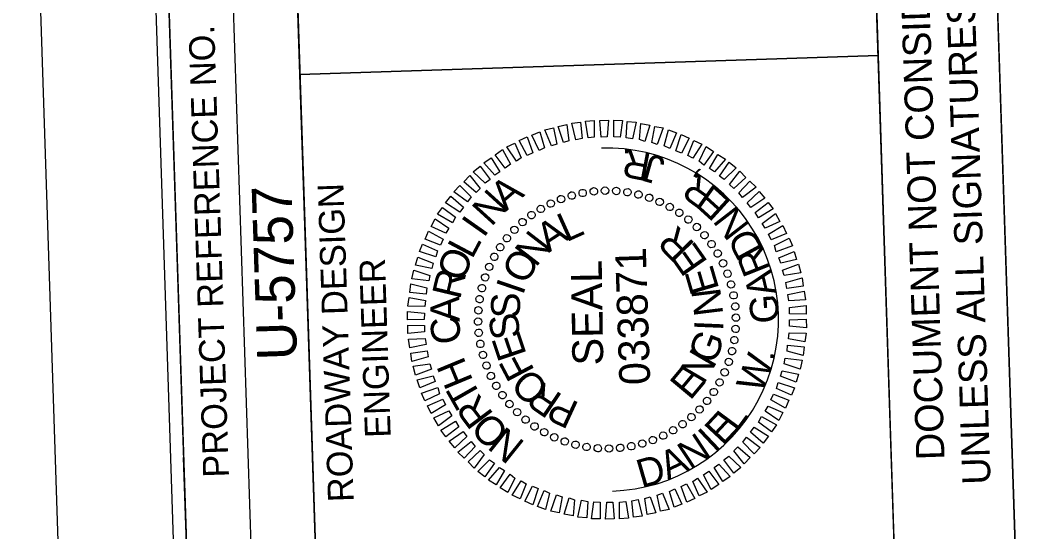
# Model space of a CAD drawing. Extents: x 1627314 to 1628469, y 762309 to 764253.
# Drawn here: x 1627314.2 to 1627512.6, y 763788.2 to 763887.6 of the extents above; entities that cross this region are included whole.
import ezdxf

# ---------------------------------------------------------------- set-up
doc = ezdxf.new("R2010")
doc.units = 0
for name, color, linetype in [('Old_Level_58', 7, 'Continuous'), ('Scratch_Level_0', 7, 'Continuous'), ('Sheet Data Field CELL', 7, 'Continuous'), ('Sheet Plot Border Inside CELL', 7, 'Continuous'), ('Sheet Plot Border Outside CELL', 7, 'Continuous'), ('Sheet Professional Seal CELL', 7, 'Continuous'), ('Sheet Profile CELL', 7, 'Continuous'), ('Sheet Profile Grid Major CELL', 7, 'Continuous'), ('Sheet Profile Grid Minor CELL', 7, 'Continuous'), ('Sheet Sticker Exception Certification CELL', 7, 'Continuous')]:
    doc.layers.add(name, color=color, linetype=linetype)

msp = doc.modelspace()

# ---------------------------------------------------------------- linework, layer by layer
at = {"layer": 'Old_Level_58'}
msp.add_lwpolyline([(1627507.79, 763781.61), (1627501.25, 763981.49), (1627565.16, 763983.58), (1627571.7, 763783.7)], close=True, dxfattribs=at)
at = {"layer": 'Scratch_Level_0'}
msp.add_arc((1627428.29, 763829.42), 33.36, 271.8735, 91.8735, dxfattribs=at)
at = {"layer": 'Sheet Plot Border Inside CELL'}
msp.add_lwpolyline([(1628446.34, 762357.53), (1628391.86, 764023.14), (1627337.33, 763988.65), (1627391.81, 762323.04)], close=True, dxfattribs=at)
at = {"layer": 'Sheet Plot Border Outside CELL'}
msp.add_lwpolyline([(1628469.21, 762345.27), (1628413.63, 764044.37), (1627314.22, 764008.4), (1627369.79, 762309.31)], close=True, dxfattribs=at)
at = {"layer": 'Sheet Professional Seal CELL'}
for p, q in [((1627425.73, 763854.4), (1627425.73, 763854.4)), ((1627427.92, 763854.52), (1627427.92, 763854.52)), ((1627430.13, 763854.45), (1627430.13, 763854.45)), ((1627419.32, 763852.89), (1627419.32, 763852.89)), ((1627421.4, 763853.56), (1627421.4, 763853.56)), ((1627423.59, 763854.03), (1627423.59, 763854.03)), ((1627432.29, 763854.17), (1627432.29, 763854.17)), ((1627434.4, 763853.79), (1627434.4, 763853.79)), ((1627436.52, 763853.16), (1627436.52, 763853.16)), ((1627438.55, 763852.32), (1627438.55, 763852.32)), ((1627415.43, 763850.96), (1627415.43, 763850.96)), ((1627417.35, 763852.03), (1627417.35, 763852.03)), ((1627440.53, 763851.39), (1627440.53, 763851.39)), ((1627411.86, 763848.45), (1627411.86, 763848.45)), ((1627413.57, 763849.75), (1627413.57, 763849.75)), ((1627442.37, 763850.19), (1627442.37, 763850.19)), ((1627444.16, 763848.9), (1627444.16, 763848.9)), ((1627410.26, 763846.89), (1627410.26, 763846.89)), ((1627445.76, 763847.45), (1627445.76, 763847.45)), ((1627408.81, 763845.3), (1627408.81, 763845.3)), ((1627447.32, 763845.85), (1627447.32, 763845.85)), ((1627407.52, 763843.5), (1627407.52, 763843.5)), ((1627448.62, 763844.15), (1627448.62, 763844.15)), ((1627406.33, 763841.66), (1627406.33, 763841.66)), ((1627449.83, 763842.28), (1627449.83, 763842.28)), ((1627450.9, 763840.37), (1627450.9, 763840.37)), ((1627405.4, 763839.68), (1627405.4, 763839.68)), ((1627451.76, 763838.4), (1627451.76, 763838.4)), ((1627404.56, 763837.65), (1627404.56, 763837.65)), ((1627403.93, 763835.53), (1627403.93, 763835.53)), ((1627452.43, 763836.32), (1627452.43, 763836.32)), ((1627403.55, 763833.42), (1627403.55, 763833.42)), ((1627452.9, 763834.13), (1627452.9, 763834.13)), ((1627403.27, 763831.26), (1627403.27, 763831.26)), ((1627453.27, 763831.99), (1627453.27, 763831.99)), ((1627403.19, 763829.05), (1627403.19, 763829.05)), ((1627428.29, 763829.42), (1627428.29, 763829.42)), ((1627453.39, 763829.79), (1627453.39, 763829.79)), ((1627403.31, 763826.86), (1627403.31, 763826.86)), ((1627453.32, 763827.59), (1627453.32, 763827.59)), ((1627403.68, 763824.72), (1627403.68, 763824.72)), ((1627453.04, 763825.43), (1627453.04, 763825.43)), ((1627404.16, 763822.53), (1627404.16, 763822.53)), ((1627452.66, 763823.32), (1627452.66, 763823.32)), ((1627452.02, 763821.2), (1627452.02, 763821.2)), ((1627404.82, 763820.45), (1627404.82, 763820.45)), ((1627451.19, 763819.17), (1627451.19, 763819.17)), ((1627405.69, 763818.48), (1627405.69, 763818.48)), ((1627406.75, 763816.56), (1627406.75, 763816.56)), ((1627450.26, 763817.19), (1627450.26, 763817.19)), ((1627407.96, 763814.7), (1627407.96, 763814.7)), ((1627449.06, 763815.35), (1627449.06, 763815.35)), ((1627409.27, 763812.99), (1627409.27, 763812.99)), ((1627447.77, 763813.55), (1627447.77, 763813.55)), ((1627410.82, 763811.39), (1627410.82, 763811.39)), ((1627446.32, 763811.95), (1627446.32, 763811.95)), ((1627412.42, 763809.94), (1627412.42, 763809.94)), ((1627414.21, 763808.65), (1627414.21, 763808.65)), ((1627443.02, 763809.09), (1627443.02, 763809.09)), ((1627444.72, 763810.4), (1627444.72, 763810.4)), ((1627416.05, 763807.46), (1627416.05, 763807.46)), ((1627439.24, 763806.82), (1627439.24, 763806.82)), ((1627441.15, 763807.88), (1627441.15, 763807.88)), ((1627418.04, 763806.53), (1627418.04, 763806.53)), ((1627420.06, 763805.69), (1627420.06, 763805.69)), ((1627422.19, 763805.06), (1627422.19, 763805.06)), ((1627424.3, 763804.68), (1627424.3, 763804.68)), ((1627433, 763804.81), (1627433, 763804.81)), ((1627435.19, 763805.29), (1627435.19, 763805.29)), ((1627437.27, 763805.95), (1627437.27, 763805.95)), ((1627426.46, 763804.4), (1627426.46, 763804.4)), ((1627428.66, 763804.32), (1627428.66, 763804.32)), ((1627430.86, 763804.44), (1627430.86, 763804.44))]:
    msp.add_line(p, q, dxfattribs=at)
for points in [[(1627424.64, 763864.77), (1627424.13, 763868.01), (1627425.83, 763868.16), (1627425.83, 763864.91)], [(1627427.13, 763864.9), (1627426.88, 763868.15), (1627428.58, 763868.2), (1627428.33, 763864.94)], [(1627429.63, 763864.94), (1627429.63, 763868.19), (1627431.28, 763868.14), (1627430.84, 763864.88)], [(1627417.48, 763863.19), (1627416.23, 763866.35), (1627417.87, 763866.7), (1627418.52, 763863.57)], [(1627419.86, 763863.87), (1627418.81, 763866.98), (1627420.5, 763867.34), (1627420.9, 763864.2)], [(1627422.25, 763864.39), (1627421.44, 763867.62), (1627423.14, 763867.83), (1627423.44, 763864.63)], [(1627432.04, 763864.76), (1627432.24, 763867.97), (1627433.94, 763867.83), (1627433.25, 763864.55)], [(1627434.6, 763864.45), (1627434.9, 763867.56), (1627436.61, 763867.27), (1627435.66, 763864.08)], [(1627437.02, 763863.88), (1627437.57, 763867), (1627439.23, 763866.7), (1627438.08, 763863.51)], [(1627439.44, 763863.21), (1627440.24, 763866.33), (1627441.81, 763865.74), (1627440.51, 763862.69)], [(1627412.79, 763861.33), (1627411.2, 763864.23), (1627412.77, 763864.94), (1627413.87, 763861.87)], [(1627415.11, 763862.31), (1627413.71, 763865.32), (1627415.24, 763865.92), (1627416.14, 763862.84)], [(1627441.68, 763862.28), (1627442.72, 763865.41), (1627444.3, 763864.72), (1627442.79, 763861.81)], [(1627444.01, 763861.35), (1627445.16, 763864.24), (1627446.74, 763863.54), (1627444.98, 763860.79)], [(1627408.52, 763858.89), (1627406.53, 763861.48), (1627408, 763862.48), (1627409.5, 763859.63)], [(1627410.68, 763860.26), (1627408.83, 763863.01), (1627410.36, 763863.71), (1627411.61, 763860.89)], [(1627446.2, 763860.23), (1627447.6, 763863.07), (1627449.04, 763862.12), (1627447.12, 763859.46)], [(1627406.51, 763857.53), (1627404.33, 763859.91), (1627405.75, 763860.9), (1627407.44, 763858.16)], [(1627448.24, 763858.79), (1627449.85, 763861.55), (1627451.33, 763860.64), (1627449.21, 763858.17)], [(1627404.61, 763855.96), (1627402.29, 763858.19), (1627403.6, 763859.28), (1627405.59, 763856.7)], [(1627450.19, 763857.35), (1627452.06, 763860.02), (1627453.39, 763858.96), (1627451.11, 763856.68)], [(1627452.15, 763855.67), (1627454.11, 763858.28), (1627455.3, 763857.07), (1627452.97, 763854.89)], [(1627402.87, 763854.16), (1627400.45, 763856.23), (1627401.61, 763857.47), (1627403.65, 763854.93)], [(1627453.95, 763854.08), (1627456.08, 763856.35), (1627457.32, 763855.19), (1627454.68, 763853.15)], [(1627401.18, 763852.3), (1627398.52, 763854.26), (1627399.68, 763855.5), (1627401.9, 763853.27)], [(1627455.57, 763852.13), (1627457.89, 763854.35), (1627458.99, 763853.04), (1627456.25, 763851.2)], [(1627399.69, 763850.35), (1627396.88, 763852.11), (1627397.94, 763853.44), (1627400.36, 763851.32)], [(1627398.26, 763848.25), (1627395.31, 763849.91), (1627396.31, 763851.24), (1627398.83, 763849.37)], [(1627457.13, 763850.28), (1627459.62, 763852.21), (1627460.61, 763850.94), (1627457.76, 763849.2)], [(1627396.98, 763846.26), (1627394.08, 763847.51), (1627394.88, 763849.04), (1627397.54, 763847.23)], [(1627458.45, 763848.12), (1627461.09, 763850.06), (1627461.94, 763848.53), (1627459.08, 763847.19)], [(1627395.9, 763843.92), (1627392.91, 763845.08), (1627393.56, 763846.65), (1627396.42, 763845.04)], [(1627459.72, 763846.01), (1627462.46, 763847.7), (1627463.21, 763846.17), (1627460.2, 763844.93)], [(1627460.84, 763843.85), (1627463.7, 763845.24), (1627464.34, 763843.76), (1627461.18, 763842.61)], [(1627395.03, 763841.64), (1627391.84, 763842.69), (1627392.39, 763844.11), (1627395.34, 763842.8)], [(1627461.72, 763841.42), (1627464.68, 763842.67), (1627465.18, 763841.14), (1627462.1, 763840.38)], [(1627394.2, 763839.36), (1627391.08, 763840.01), (1627391.53, 763841.58), (1627394.52, 763840.43)], [(1627393.63, 763836.94), (1627390.36, 763837.34), (1627390.71, 763839.05), (1627393.84, 763838)], [(1627462.45, 763839.05), (1627465.56, 763840.2), (1627465.97, 763838.51), (1627462.73, 763838)], [(1627393.16, 763834.38), (1627389.95, 763834.72), (1627390.15, 763836.38), (1627393.27, 763835.58)], [(1627463.08, 763836.66), (1627466.25, 763837.57), (1627466.45, 763835.92), (1627463.26, 763835.47)], [(1627463.45, 763834.28), (1627466.63, 763834.93), (1627466.89, 763833.24), (1627463.64, 763833.08)], [(1627392.84, 763831.97), (1627389.59, 763832.06), (1627389.83, 763833.72), (1627393, 763833.17)], [(1627392.77, 763829.46), (1627389.52, 763829.36), (1627389.52, 763831.01), (1627392.78, 763830.66)], [(1627463.79, 763831.79), (1627467.03, 763832.14), (1627467.03, 763830.49), (1627463.77, 763830.58)], [(1627463.81, 763829.38), (1627467.06, 763829.49), (1627467.07, 763827.84), (1627463.8, 763828.18)], [(1627392.8, 763827.06), (1627389.56, 763826.71), (1627389.56, 763828.36), (1627392.81, 763828.26)], [(1627463.75, 763826.88), (1627467, 763826.79), (1627466.75, 763825.13), (1627463.58, 763825.68)], [(1627393.13, 763824.57), (1627389.95, 763823.92), (1627389.7, 763825.61), (1627392.94, 763825.77)], [(1627463.42, 763824.47), (1627466.64, 763824.12), (1627466.44, 763822.47), (1627463.31, 763823.27)], [(1627393.51, 763822.18), (1627390.34, 763821.28), (1627390.14, 763822.92), (1627393.32, 763823.38)], [(1627394.14, 763819.8), (1627391.03, 763818.65), (1627390.62, 763820.34), (1627393.86, 763820.84)], [(1627462.96, 763821.9), (1627466.22, 763821.51), (1627465.88, 763819.8), (1627462.74, 763820.85)], [(1627462.39, 763819.48), (1627465.51, 763818.83), (1627465.06, 763817.27), (1627462.07, 763818.42)], [(1627394.87, 763817.42), (1627391.91, 763816.18), (1627391.41, 763817.71), (1627394.48, 763818.46)], [(1627461.56, 763817.2), (1627464.75, 763816.16), (1627464.19, 763814.74), (1627461.25, 763816.04)], [(1627395.75, 763815), (1627392.89, 763813.61), (1627392.24, 763815.09), (1627395.41, 763816.24)], [(1627460.68, 763814.92), (1627463.67, 763813.77), (1627463.02, 763812.2), (1627460.17, 763813.81)], [(1627396.87, 763812.84), (1627394.12, 763811.15), (1627393.37, 763812.67), (1627396.38, 763813.92)], [(1627459.61, 763812.59), (1627462.5, 763811.33), (1627461.7, 763809.81), (1627459.04, 763811.62)], [(1627398.14, 763810.73), (1627395.5, 763808.79), (1627394.65, 763810.31), (1627397.51, 763811.66)], [(1627458.32, 763810.6), (1627461.28, 763808.94), (1627460.27, 763807.61), (1627457.76, 763809.48)], [(1627399.46, 763808.57), (1627396.97, 763806.64), (1627395.98, 763807.91), (1627398.82, 763809.65)], [(1627401.02, 763806.72), (1627398.69, 763804.49), (1627397.6, 763805.81), (1627400.34, 763807.65)], [(1627456.89, 763808.5), (1627459.7, 763806.74), (1627458.64, 763805.4), (1627456.22, 763807.53)], [(1627402.64, 763804.77), (1627400.51, 763802.5), (1627399.27, 763803.66), (1627401.9, 763805.7)], [(1627453.72, 763804.69), (1627456.13, 763802.62), (1627454.97, 763801.38), (1627452.94, 763803.92)], [(1627455.41, 763806.55), (1627458.07, 763804.58), (1627456.91, 763803.35), (1627454.69, 763805.57)], [(1627404.44, 763803.18), (1627402.47, 763800.56), (1627401.28, 763801.78), (1627403.61, 763803.95)], [(1627451.97, 763802.88), (1627454.3, 763800.66), (1627452.98, 763799.56), (1627451, 763802.15)], [(1627406.39, 763801.49), (1627404.53, 763798.83), (1627403.2, 763799.89), (1627405.47, 763802.16)], [(1627408.34, 763800.06), (1627406.73, 763797.3), (1627405.25, 763798.2), (1627407.37, 763800.67)], [(1627450.07, 763801.32), (1627452.25, 763798.94), (1627450.83, 763797.94), (1627449.14, 763800.69)], [(1627410.39, 763798.62), (1627408.98, 763795.77), (1627407.55, 763796.73), (1627409.46, 763799.39)], [(1627448.07, 763799.95), (1627450.05, 763797.37), (1627448.58, 763796.37), (1627447.09, 763799.22)], [(1627412.58, 763797.49), (1627411.42, 763794.6), (1627409.85, 763795.3), (1627411.61, 763798.06)], [(1627414.91, 763796.57), (1627413.86, 763793.43), (1627412.29, 763794.13), (1627413.79, 763797.03)], [(1627443.79, 763797.51), (1627445.39, 763794.61), (1627443.81, 763793.91), (1627442.71, 763796.98)], [(1627445.91, 763798.58), (1627447.75, 763795.84), (1627446.22, 763795.14), (1627444.98, 763797.95)], [(1627417.14, 763795.64), (1627416.34, 763792.51), (1627414.77, 763793.11), (1627416.07, 763796.16)], [(1627419.56, 763794.97), (1627419.02, 763791.85), (1627417.36, 763792.15), (1627418.5, 763795.34)], [(1627421.98, 763794.4), (1627421.69, 763791.29), (1627419.98, 763791.58), (1627420.92, 763794.76)], [(1627436.72, 763794.98), (1627437.78, 763791.86), (1627436.09, 763791.51), (1627435.68, 763794.65)], [(1627439.1, 763795.66), (1627440.36, 763792.5), (1627438.72, 763792.14), (1627438.06, 763795.27)], [(1627441.48, 763796.54), (1627442.87, 763793.53), (1627441.34, 763792.93), (1627440.44, 763796)], [(1627424.55, 763794.08), (1627424.35, 763790.87), (1627422.65, 763791.02), (1627423.34, 763794.29)], [(1627426.95, 763793.91), (1627426.96, 763790.66), (1627425.31, 763790.71), (1627425.75, 763793.97)], [(1627429.45, 763793.94), (1627429.71, 763790.7), (1627428.01, 763790.64), (1627428.25, 763793.9)], [(1627431.95, 763794.07), (1627432.46, 763790.84), (1627430.76, 763790.68), (1627430.75, 763793.94)], [(1627434.34, 763794.45), (1627435.15, 763791.23), (1627433.45, 763791.02), (1627433.15, 763794.21)]]:
    msp.add_lwpolyline(points, close=True, dxfattribs=at)
for centre, major_axis in [((1627421.43, 763853.55), (-0.197, 0.693)), ((1627423.56, 763854.05), (-0.136, 0.707)), ((1627425.73, 763854.37), (-0.074, 0.716)), ((1627427.91, 763854.5), (-0.011, 0.72)), ((1627430.1, 763854.44), (0.052, 0.718)), ((1627432.27, 763854.19), (0.114, 0.711)), ((1627434.41, 763853.75), (0.176, 0.698)), ((1627417.35, 763851.99), (-0.314, 0.648)), ((1627419.36, 763852.86), (-0.257, 0.673)), ((1627436.51, 763853.12), (0.236, 0.68)), ((1627438.54, 763852.31), (0.294, 0.657)), ((1627413.6, 763849.75), (-0.422, 0.583)), ((1627415.42, 763850.95), (-0.369, 0.618)), ((1627440.5, 763851.33), (0.35, 0.629)), ((1627442.36, 763850.18), (0.404, 0.596)), ((1627411.88, 763848.39), (-0.471, 0.544)), ((1627444.12, 763848.88), (0.454, 0.559)), ((1627410.29, 763846.89), (-0.517, 0.501)), ((1627445.76, 763847.43), (0.501, 0.517)), ((1627447.26, 763845.84), (0.544, 0.471)), ((1627407.53, 763843.49), (-0.596, 0.404)), ((1627408.84, 763845.25), (-0.559, 0.454)), ((1627448.62, 763844.12), (0.583, 0.422)), ((1627406.38, 763841.63), (-0.629, 0.35)), ((1627449.82, 763842.29), (0.618, 0.369)), ((1627405.4, 763839.68), (-0.657, 0.294)), ((1627450.86, 763840.37), (0.648, 0.314)), ((1627404.6, 763837.64), (-0.68, 0.236)), ((1627451.73, 763838.36), (0.673, 0.257)), ((1627403.97, 763835.54), (-0.698, 0.176)), ((1627452.42, 763836.28), (0.693, 0.197)), ((1627452.92, 763834.15), (0.707, 0.136)), ((1627403.53, 763833.4), (-0.711, 0.114)), ((1627453.24, 763831.99), (0.716, 0.074)), ((1627403.28, 763831.23), (-0.718, 0.052)), ((1627453.37, 763829.81), (0.72, 0.011)), ((1627403.22, 763829.04), (-0.72, -0.011)), ((1627403.34, 763826.86), (-0.716, -0.074)), ((1627453.31, 763827.62), (0.718, -0.052)), ((1627403.66, 763824.69), (-0.707, -0.136)), ((1627453.06, 763825.45), (0.711, -0.114)), ((1627404.17, 763822.56), (-0.693, -0.197)), ((1627452.61, 763823.3), (0.698, -0.176)), ((1627404.86, 763820.49), (-0.673, -0.257)), ((1627451.99, 763821.21), (0.68, -0.236)), ((1627405.73, 763818.48), (-0.648, -0.314)), ((1627451.18, 763819.17), (0.657, -0.294)), ((1627406.77, 763816.55), (-0.618, -0.369)), ((1627450.2, 763817.22), (0.629, -0.35)), ((1627407.97, 763814.73), (-0.583, -0.422)), ((1627449.05, 763815.35), (0.596, -0.404)), ((1627409.33, 763813.01), (-0.544, -0.471)), ((1627446.3, 763811.96), (0.517, -0.501)), ((1627447.75, 763813.6), (0.559, -0.454)), ((1627410.83, 763811.42), (-0.501, -0.517)), ((1627412.47, 763809.97), (-0.454, -0.559)), ((1627444.71, 763810.46), (0.471, -0.544)), ((1627414.22, 763808.66), (-0.404, -0.596)), ((1627441.16, 763807.9), (0.369, -0.618)), ((1627442.99, 763809.1), (0.422, -0.583)), ((1627416.09, 763807.52), (-0.35, -0.629)), ((1627418.04, 763806.53), (-0.294, -0.657)), ((1627437.23, 763805.99), (0.257, -0.673)), ((1627439.24, 763806.86), (0.314, -0.648)), ((1627420.08, 763805.73), (-0.236, -0.68)), ((1627422.17, 763805.1), (-0.176, -0.698)), ((1627424.32, 763804.66), (-0.114, -0.711)), ((1627426.49, 763804.41), (-0.052, -0.718)), ((1627428.68, 763804.35), (0.011, -0.72)), ((1627430.86, 763804.48), (0.074, -0.716)), ((1627433.02, 763804.79), (0.136, -0.707)), ((1627435.15, 763805.3), (0.197, -0.693))]:
    msp.add_ellipse(centre, major_axis=major_axis, ratio=0.999708, dxfattribs=at)
at = {"layer": 'Sheet Profile CELL'}
for p, q in [((1627359.37, 763776.71), (1627352.83, 763976.65)), ((1627368.59, 763877.11), (1627480.98, 763880.79))]:
    msp.add_line(p, q, dxfattribs=at)
for points in [[(1627340.28, 763976.24), (1627389.32, 762477.04), (1628438.76, 762511.37), (1628389.72, 764010.57)], [(1627368.59, 763877.11), (1627365.32, 763977.06), (1627477.76, 763980.74), (1627481.03, 763880.79)], [(1627346.82, 763776.3), (1627340.28, 763976.24), (1627365.32, 763977.06), (1627371.86, 763777.12)], [(1627371.86, 763777.12), (1627368.59, 763877.11), (1627481.03, 763880.79), (1627484.3, 763780.79)]]:
    msp.add_lwpolyline(points, close=True, dxfattribs=at)
at = {"layer": 'Sheet Profile Grid Major CELL'}
msp.add_lwpolyline([(1627363.17, 763276.61), (1627361.53, 763326.59), (1627861.27, 763342.93), (1627859.63, 763392.91), (1627359.9, 763376.56), (1627358.26, 763426.53), (1627858, 763442.88), (1627856.36, 763492.85), (1627356.63, 763476.51), (1627354.99, 763526.48), (1627854.73, 763542.83), (1627853.09, 763592.8), (1627353.36, 763576.45), (1627351.73, 763626.43), (1627851.46, 763642.77), (1627849.82, 763692.75), (1627350.09, 763676.4), (1627348.46, 763726.37), (1627848.19, 763742.72), (1627846.55, 763792.69), (1627346.82, 763776.35), (1627345.96, 763802.63)], dxfattribs=at)
at = {"layer": 'Sheet Sticker Exception Certification CELL'}
for p, q in [((1627501.25, 763981.49), (1627507.79, 763781.56)), ((1627501.25, 763981.49), (1627507.79, 763781.56)), ((1627484.3, 763780.79), (1627477.76, 763980.72)), ((1627484.3, 763780.79), (1627477.76, 763980.72))]:
    msp.add_line(p, q, dxfattribs=at)

# ---------------------------------------------------------------- texts
at = {"layer": 'Sheet Data Field CELL'}
msp.add_text('U-5757', height=7.75, rotation=91.8735, dxfattribs=at).set_placement((1627368.04, 763821.64))
at = {"layer": 'Sheet Professional Seal CELL'}
for s, height, rotation, p in [('A', 5.64, 40.4906, (1627408.65, 763850.39)), ('N', 5.64, 47.6924, (1627405.8, 763847.35)), ('I', 5.64, 54.8936, (1627404.32, 763845.15)), ('A', 5.64, 33.6337, (1627416.96, 763842.36)), ('L', 5.64, 24.2743, (1627420.35, 763844.42)), ('N', 5.64, 52.3501, (1627414.46, 763839.43)), ('R', 5.64, 134.3549, (1627445.57, 763844.1)), ('L', 5.64, 62.0943, (1627402.05, 763841.02)), ('E', 5.64, 124.9976, (1627448.04, 763840.63)), ('O', 5.64, 69.2946, (1627400.34, 763836.56)), ('O', 5.64, 61.707, (1627412.57, 763836.01)), ('SEAL', 5.998, 90.8735, (1627427.58, 763820.55)), ('R', 5.64, 76.4946, (1627399.7, 763833.19)), ('E', 5.64, 106.2852, (1627450.16, 763835.39)), ('I', 5.64, 71.0631, (1627411.94, 763833.99)), ('S', 5.64, 89.7739, (1627411.38, 763829.67)), ('N', 5.64, 96.9299, (1627450.92, 763830.46)), ('A', 5.64, 90.8938, (1627399.64, 763828.99)), ('S', 5.64, 99.1291, (1627411.54, 763826.07)), ('C', 5.64, 98.0933, (1627400.07, 763825.05)), ('I', 5.64, 87.5747, (1627450.88, 763827.11)), ('E', 5.64, 108.4845, (1627412.71, 763822.66)), ('G', 5.64, 68.8637, (1627449.2, 763820.5)), ('N', 5.64, 59.5074, (1627447.07, 763816.63)), ('H', 5.64, 112.4929, (1627402.32, 763817.52)), ('F', 5.64, 117.8405, (1627414.31, 763819.51)), ('E', 5.64, 50.1504, (1627444.47, 763813.54)), ('O', 5.64, 136.5547, (1627417.37, 763816.31)), ('T', 5.64, 119.6932, (1627404.07, 763814.32)), ('R', 5.64, 145.9131, (1627419.87, 763814.64)), ('R', 5.64, 126.894, (1627406.38, 763811)), ('P', 5.64, 155.2724, (1627423.12, 763813.15)), ('O', 5.64, 134.0952, (1627409.6, 763807.65)), ('N', 5.64, 141.297, (1627412.57, 763805.45))]:
    msp.add_text(s, height=height, rotation=rotation, dxfattribs=at).set_placement(p)
at = {"layer": 'Sheet Profile CELL'}
for s, height, p in [('PROJECT REFERENCE NO.', 5.0001, (1627354.78, 763798.78)), ('ROADWAY DESIGN', 5.0001, (1627379.05, 763794.02)), ('ENGINEER', 5, (1627386.24, 763806.51))]:
    msp.add_text(s, height=height, rotation=91.8735, dxfattribs=at).set_placement(p)
at = {"layer": 'Sheet Profile Grid Minor CELL'}
for s, height, rotation, p in [('R', 5.5, 169.2275, (1627437.14, 763861.7)), ('.', 5.5, 176.154, (1627433.19, 763862.53)), ('J', 5.5, 164.359, (1627439.85, 763860.83)), (',', 5.5, 151.1787, (1627446.71, 763857.37)), ('R', 5.5, 144.2523, (1627449.95, 763854.95)), ('E', 5.5, 137.6693, (1627452.73, 763852.3)), ('N', 5.5, 127.7376, (1627456.31, 763847.74)), ('D', 5.5, 118.5929, (1627458.86, 763843.05)), ('033871', 5.998, 91.8735, (1627436.72, 763816.79)), ('R', 5.5, 111.6665, (1627460.28, 763839.27)), ('A', 5.5, 103.4807, (1627461.36, 763834.61)), ('G', 5.5, 93.549, (1627461.76, 763828.83)), ('W', 5.5, 68.7626, (1627458.43, 763814.86)), ('.', 5.5, 80.3687, (1627460.74, 763821.22)), ('E', 5.5, 46.9243, (1627450.85, 763804.69)), ('L', 5.5, 53.5073, (1627453.53, 763807.44)), ('N', 5.5, 33.4721, (1627444.47, 763800.12)), ('I', 5.5, 43.4038, (1627449.28, 763803.35)), ('D', 5.5, 16.1417, (1627435.01, 763796.63)), ('A', 5.5, 25.2863, (1627440.14, 763798.12))]:
    msp.add_text(s, height=height, rotation=rotation, dxfattribs=at).set_placement(p)
at = {"layer": 'Sheet Sticker Exception Certification CELL'}
for s, p in [('UNLESS ALL SIGNATURES COMPLETED', (1627502.91, 763797.41)), ('UNLESS ALL SIGNATURES COMPLETED', (1627502.91, 763797.41)), ('DOCUMENT NOT CONSIDERED FINAL', (1627493.95, 763802.19)), ('DOCUMENT NOT CONSIDERED FINAL', (1627493.95, 763802.19))]:
    msp.add_text(s, height=5.5, rotation=91.8735, dxfattribs=at).set_placement(p)

doc.saveas('drawing.dxf')
